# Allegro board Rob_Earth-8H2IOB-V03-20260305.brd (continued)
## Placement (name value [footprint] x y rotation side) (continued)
HOLE3601  -  [HOLE-C5_0D2_2]  47.5 86.5 0 top
HOLE3602  -  [HOLE-C5_0D2_2]  195 5 0 top
HOLE3603  -  [HOLE-C5_0D2_2]  140 5 0 top
HOLE3604  -  [HOLE-C5_0D2_2]  120.5 20 0 top
HOLE3605  -  [HOLE-C5_0D2_2]  47.5 3 0 top
HOLE3606  -  [HOLE-C5_0D2_2]  5 5 0 top
HOLE3607  -  [HOLE-C5_0D2_2]  195 125 0 top
HOLE3608  -  [HOLE-C5_0D2_2]  120.5 86.5 0 top
HOLE3609  -  [HOLE-C5_0D2_2]  140 125 0 top
HOLE3610  -  [HOLE-C5_0D2_2]  60 125 0 top
HOLE3611  -  [HOLE-C5_0D2_2]  5 125 0 top
J501  039301040  [HD2X2-H10-123-39-30-1040]  185.13 20.84 90 top
J1200  161655051  [HDMI19-H16_4-161655051]  7.5 21.15 270 top
J1201  161655051  [HDMI19-H16_4-161655051]  7.5 33.52 270 top
J1300  161655051  [HDMI19-H16_4-161655051]  7.5 45.9 270 top
J1500  LB2016RJ10P1330-11  [RJ45-14P-H13_3-LB2016RJ10P1330-11]  8.7 108.97 270 top
J1600  53398067  [WTB6U-1_25H5_7-53398]  131.25 91.76 270 top
J1900  LB-US3RJ01-02  [CON30-H31-LB-US3RJ02-01]  194.75 85.66 90 top
J1901  LB-US3RJ01-02  [CON30-H31-LB-US3RJ02-01]  194.75 107.61 90 top
J2000  LB-US3RJ01-02  [CON30-H31-LB-US3RJ02-01]  194.75 41.76 90 top
J2001  LB-US3RJ01-02  [CON30-H31-LB-US3RJ02-01]  194.75 63.7 90 top
J2600  SEAF-40-06.0-S-06-2-A-K-TR  [BTB240F-1_27H6_05-SEAF-40]  50 45 90 top
J2700  SEAF-20-06.0-L-10-2-A-K-TR  [BTB200F-1_27H6_05-SEAF-20]  115.5 40 270 top
J2800  BS-08-B2AA001  [BAT2-25_2X20H5_3]  79.49 23.34 0 bottom
J2801  SM02B-PASS-TB  [WTB2S-2H5_7-SM03B-PASS-TB]  87.16 124.24 0 top
J2802  SM02B-PASS-TB  [WTB2S-2H5_7-SM03B-PASS-TB]  75.76 124.24 0 top
J3301  533980271  [WTB2U-1_25H5_7-53398]  98.9 125.44 180 top
J3302  533980271  [WTB2U-1_25H5_7-53398]  131.22 125.46 180 top
J3303  533980371  [WTB3U-1_25H5_7-53398]  150.44 125.4 180 top
J3304  533980271  [WTB2U-1_25H5_7-53398]  120.32 125.45 180 top
J3305  533980271  [WTB2U-1_25H5_7-53398]  109.62 125.45 180 top
J3310  533980571  [WTB5U-1_25H5_7-53398]  163.73 125.41 180 top
J3400  BRA-ST-20102001S-2.8  [HDS2X10-2H6_8-123-BRA-ST]  143.85 34.57 180 top
J3500  53398067  [WTB6U-1_25H5_7-53398]  44.93 125.37 180 top
J3501  53398067  [WTB6U-1_25H5_7-53398]  26.5 125.45 180 top
J3600  47053-1000  [HD4X1-2_54H10-47053-1000]  183.29 3.71 180 top
J3601  47053-1000  [HD4X1-2_54H10-47053-1000]  168.08 3.71 180 top
JP502  Short_L1  [SP2-L1]  120.83 62.15 0 bottom
JP503  Short_L1  [SP2-L1]  120.07 62.48 90 bottom
JP504  Short_L1  [SP2-L1]  99.35 87.08 270 bottom
JP505  Short_L1  [SP2-L1]  99.36 88.24 90 bottom
JP600  Short_L1  [SP2-L1]  67.95 59.67 0 bottom
JP601  Short_L1  [SP2-L1]  65.95 59.67 180 bottom
JP900  power-Short_L5  [SP2-L3P]  40.14 28.08 90 bottom
JP901  power-Short_L5  [SP2-L3P]  28.94 22.6 90 bottom
JP902  power-Short_L5  [SP2-L3P]  28.37 20.41 180 bottom
JP903  power-Short_L5  [SP2-L3P]  31.26 20.07 90 bottom
JP904  power-Short_L5  [SP2-L3P]  30.65 15.72 270 bottom
JP905  power-Short_L5  [SP2-L3P]  30.62 24.84 90 bottom
JP906  power-Short_L5  [SP2-L3P]  38.13 27.72 180 bottom
JP907  power-Short_L5  [SP2-L3P]  36.9 29.06 270 bottom
JP908  power-Short_L5  [SP2-L3P]  31.2 21.83 90 bottom
JP909  power-Short_L5  [SP2-L3P]  38.97 14.54 270 bottom
JP1000  power-Short_L5  [SP2-L3P]  51.63 25.68 90 bottom
JP1001  power-Short_L5  [SP2-L3P]  60.57 28.44 180 bottom
JP1002  power-Short_L5  [SP2-L3P]  60.59 30.14 180 bottom
JP1003  power-Short_L5  [SP2-L3P]  61.61 30.97 0 bottom
JP1004  power-Short_L5  [SP2-L3P]  61.11 34.65 90 bottom
JP1005  power-Short_L5  [SP2-L3P]  61.13 25.9 270 bottom
JP1006  power-Short_L5  [SP2-L3P]  52.87 22.95 180 bottom
JP1007  power-Short_L5  [SP2-L3P]  52.18 24.09 180 bottom
JP1008  power-Short_L5  [SP2-L3P]  60.58 29.29 180 bottom
JP1009  power-Short_L5  [SP2-L3P]  56.31 37.56 0 bottom
JP1100  power-Short_L5  [SP2-L3P]  36.37 36.05 90 bottom
JP1101  power-Short_L5  [SP2-L3P]  45.18 38.99 180 bottom
JP1102  power-Short_L5  [SP2-L3P]  47.37 40.68 180 bottom
JP1103  power-Short_L5  [SP2-L3P]  35.08 42.78 90 bottom
JP1104  power-Short_L5  [SP2-L3P]  46.32 44.85 0 bottom
JP1105  power-Short_L5  [SP2-L3P]  46.25 35.83 0 bottom
JP1106  power-Short_L5  [SP2-L3P]  37.71 33.38 0 bottom
JP1107  power-Short_L5  [SP2-L3P]  37.17 35.96 90 bottom
JP1108  power-Short_L5  [SP2-L3P]  45.29 39.83 180 bottom
JP1109  power-Short_L5  [SP2-L3P]  37.32 47.37 90 bottom
L500  10uH/16A  [SL-SQ16_9H7-TMPC1707HP]  155.02 16.34 90 bottom
L501  1.5uH/15.6A  [SL-10_7X10H5_4]  110.75 67.7 180 bottom
L502  1.5uH/15.6A  [SL-10_7X10H5_4]  108.88 80.97 90 bottom
L503  10uH/16A  [SL-SQ16_9H7-TMPC1707HP]  160.32 19.63 270 top
L600  2.2uH/12A  [SL-10_7X10H4_0]  74.38 67.76 180 bottom
L700  4.7uH/25.4A  [SL-11_9X11H10_0]  99.6 49.15 180 bottom
L800  4.7uH  [SL5020-3-5_4X5_1H2]  115.33 12.45 0 bottom
L801  1uH/4.4A  [SL2016-1_85H0_8]  53.7 43.54 180 bottom
L802  0.47uH  [SL2520-1_7H1_2]  52.19 110.8 270 bottom
L803  1uH/4.4A  [SL2016-1_85H0_8]  142.15 88.22 270 top
L1400  2.2uH/2.6A  [SL2016-1_85H0_8]  89.58 111.54 90 top
L1700  2.2uH/2.6A  [SL2016-1_85H0_8]  137.95 57.94 90 top
L2800  10uH/7.2A  [SL-7_3X7_3H5_4-TMPV0754SV]  93.3 114.9 90 bottom
L2801  10uH/7.2A  [SL-7_3X7_3H5_4-TMPV0754SV]  85.5 114.9 90 bottom
L2802  10uH/7.2A  [SL-7_3X7_3H5_4-TMPV0754SV]  77.75 114.9 90 bottom
L2803  10uH/7.2A  [SL-7_3X7_3H5_4-TMPV0754SV]  69.95 114.9 90 bottom
L2900  22uH/1.28A  [SL-4_0X4_0H1_2]  20.91 99.2 0 bottom
L2901  0.56uH/1.2A  [SL0805H1_0]  16.93 97.81 0 bottom
L2902  22uH/1.28A  [SL-4_0X4_0H1_2]  22.4 92.32 0 bottom
L2903  0.56uH/1.2A  [SL0805H1_0]  18.35 91.82 0 bottom
L2904  22uH/1.28A  [SL-4_0X4_0H1_2]  20.84 86.88 0 bottom
L2905  0.56uH/1.2A  [SL0805H1_0]  16.77 87.76 0 bottom
L2906  22uH/1.28A  [SL-4_0X4_0H1_2]  22.2 80.62 0 bottom
L2907  0.56uH/1.2A  [SL0805H1_0]  18.22 81.84 0 bottom
L3000  22uH/1.28A  [SL-4_0X4_0H1_2]  18.85 76.12 0 bottom
L3001  0.56uH/1.2A  [SL0805H1_0]  16.5 73.03 0 bottom
L3002  22uH/1.28A  [SL-4_0X4_0H1_2]  22.86 68.4 0 bottom
L3003  0.56uH/1.2A  [SL0805H1_0]  17.98 66.94 0 bottom
L3004  22uH/1.28A  [SL-4_0X4_0H1_2]  21.28 62.85 0 bottom
L3005  0.56uH/1.2A  [SL0805H1_0]  17.84 62.35 90 bottom
L3006  22uH/1.28A  [SL-4_0X4_0H1_2]  22.52 56.06 0 bottom
L3007  0.56uH/1.2A  [SL0805H1_0]  18.52 56.89 0 bottom
L3200  1uH/4.4A  [SL2016-1_85H0_8]  53.28 65.72 180 bottom
LED500  RED  [LED0603H0_4]  101.48 94.88 180 top
LED1700  YELLOW GREEN  [LED0603X2H0_35]  132.28 54.53 0 top
LED3101  BLUE  [LED0603H0_8]  41.05 61.38 180 top
M3602  0.5mm  [MARK]  11.67 8.38 180 bottom
M3603  0.5mm  [MARK]  189.22 121.46 180 bottom
M3605  0.5mm  [MARK]  191.29 10.06 0 top
M3606  0.5mm  [MARK]  9.61 121.67 0 top
NOREF  -  [unnamed]  52 3 0 top
NOREF#2  -  [unnamed]  195 11 0 top
NOREF#3  -  [#2]  45.7 100.77 0 top
NOREF#4  -  [unnamed]  116 86.5 0 top
NOREF#5  -  [unnamed]  13 125 0 top
NUT2301  JYJ5034520043  [NUT-C5_2D2_8H3_1]  153.29 120.13 0 bottom
Q501  DMT69M5LCG-7  [DFN3333-8-H0_8]  96.01 81.23 180 bottom
Q502  DMT69M5LCG-7  [DFN3333-8-H0_8]  99.5 67.6 90 bottom
Q503  DMT69M5LCG-7  [DFN3333-8-H0_8]  100.48 75.87 180 bottom
Q504  DMT69M5LCG-7  [DFN3333-8-H0_8]  101.8 62.15 0 bottom
Q505  DMT69M5LCG-7  [DFN3333-8-H0_8]  144.15 23.05 90 bottom
Q506  DMT69M5LCG-7  [DFN3333-8-H0_8]  137.75 25.35 180 bottom
Q507  LMBT3904LT1G  [SOT23H1_1]  139.2 15.95 0 bottom
Q600  DMT69M5LCG-7  [DFN3333-8-H0_8]  79.64 55.78 0 bottom
Q601  DMT69M5LCG-7  [DFN3333-8-H0_8]  75.08 60.21 90 bottom
Q700  DMT69M5LCG-7  [DFN3333-8-H0_8]  110.15 39.1 90 bottom
Q701  DMT69M5LCG-7  [DFN3333-8-H0_8]  106.05 39.25 90 bottom
Q702  DMT69M5LCG-7  [DFN3333-8-H0_8]  91.95 37.95 270 bottom
Q703  DMT69M5LCG-7  [DFN3333-8-H0_8]  96.1 41.25 270 bottom
Q1400  WM02N08F  [DFN1006-3-H0_55]  104.44 112.04 180 top
Q3101  LN2306EFLT1G  [SOT23H1_1]  40.36 58.98 0 top
R500  100K_2  [0402]  125.45 22.21 180 bottom
R501  2.2K_2  [0402]  130.45 21.56 0 bottom
R502  0_2  [0402]  91.81 77.84 90 bottom
R503  3.3/F_2  [0402]  93.25 66.62 180 bottom
R504  0R003/F_2512  [SR2512H0_65]  122.72 66.12 180 bottom
R505  3.3/F_2  [0402]  93.95 77.49 180 bottom
R506  0R003/F_2512  [SR2512H0_65]  101.7 87.5 90 bottom
R507  0_2  [0402]  89.3 67.4 90 bottom
R508  0_2  [0402]  90.16 77.83 270 bottom
R509  0_2  [0402]  86.14 71.46 0 bottom
R510  0_2  [0402]  86.14 72.31 0 bottom
R511  0_2  [0402]  84.86 71.43 270 bottom
R512  18.7K/F_2  [0402]  87.64 67.4 270 bottom
R513  49.9K/F_2  [0402]  86.14 74.04 180 bottom
R514  RES_PAD_6  [1206_SP]  132.13 27.38 90 top
R515  10K_2  [0402]  92.78 77.83 270 bottom
R516  RES_PAD_6  [1206_SP]  171.65 8.4 270 bottom
R517  0R010/F_6  [SR1206]  115.55 49.75 90 bottom
R518  0R010/F_6  [SR1206]  90.65 85.75 90 bottom
R519  NC 0R010/F_6  [SR1206]  143.95 26.3 180 bottom
R520  100K/F_2  [0402]  179.53 123.71 90 top
R521  10K_2  [0402]  129.82 19.67 270 bottom
R522  15K_2  [0402]  131.3 10.72 90 bottom
R523  10K_2  [0402]  130.67 19.67 270 bottom
R524  3.3/F_2  [0402]  175.11 124.64 0 top
R525  3.3/F_2  [0402]  175.12 123.74 180 top
R526  10K_2  [0402]  178.2 127.4 180 top
R527  2.2K_2  [0402]  133.3 16.2 180 bottom
R528  27K/F_2  [0402]  177.77 124.5 90 top
R529  100_2  [0402]  127.05 19.7 90 bottom
R530  10K/F_2  [0402]  178.18 126.55 0 top
R531  10K_2  [0402]  136 19.05 180 bottom
R532  10K_2  [0402]  92.08 67.55 90 bottom
R533  NC 10K_2  [0402]  86.45 76.1 270 bottom
R534  1K_2  [0402]  102.19 92.79 270 top
R535  34.8K/F_2  [0402]  178.62 124.5 90 top
R536  39K/F_2  [0402]  178.18 125.7 0 top
R537  3.3/F_2  [0402]  125.39 30.4 180 top
R538  1K_2  [0402]  127.23 39.87 0 top
R539  0_2  [0402]  92.25 79.48 270 bottom
R540  14K/F_2  [0402]  89.31 77.84 90 bottom
R541  100K/F_2  [0402]  90.95 67.4 270 bottom
R542  NC 0_2  [0402]  90.12 67.4 90 bottom
R543  243K/F_2  [0402]  88.46 65.85 270 bottom
R544  14K/F_2  [0402]  89.31 65.86 270 bottom
R600  NC 10K_2  [0402]  73.84 52.86 0 bottom
R601  1/F_2  [0402]  73.84 54.11 0 bottom
R602  10K_2  [0402]  69.59 57.36 180 bottom
R603  NC 10K_2  [0402]  71.89 49.81 90 bottom
R604  10K_2  [0402]  69.94 49.81 90 bottom
R605  0R010/F_6  [SR1206]  66.96 61.39 180 bottom
R606  1/F_2  [0402]  71.64 57.71 90 bottom
R607  86.6K/F_2  [0402]  66.19 54.01 0 bottom
R608  NC 0_2  [0402]  68.79 58.21 180 bottom
R609  0R010/F_6  [SR1206]  85.35 57.3 270 bottom
R610  0_2  [0402]  71.04 49.81 270 bottom
R611  NC 100K_2  [0402]  69.09 49.81 270 bottom
R612  10K/F_2  [0402]  66.18 55.7 180 bottom
R613  34.8K/F_2  [0402]  68.24 49.81 270 bottom
R614  100K_2  [0402]  66.19 52.16 180 bottom
R700  0R010/F_6  [SR1206]  121.6 38.45 180 bottom
R701  10/F_2  [0402]  106.05 35.5 180 bottom
R702  10/F_2  [0402]  107.23 35.85 90 bottom
R703  0R002/F_6  [SR1206]  104.9 42.2 180 bottom
R704  NC 10K_2  [0402]  105.13 24.85 270 bottom
R705  NC 10K_2  [0402]  103.33 24.85 90 bottom
R706  9.09K/F_2  [0402]  104.23 24.85 270 bottom
R707  130K/F_2  [0402]  95.65 30.4 270 bottom
R708  9.09K/F_2  [0402]  97.43 23.15 270 bottom
R709  8.25K/F_2  [0402]  101.03 24.75 270 bottom
R710  110K/F_2  [0402]  100.13 24.75 270 bottom
R711  84.5K/F_2  [R0402]  99.23 24.75 270 bottom
R712  5.62K/F_2  [0402]  95.65 28.85 270 bottom
R713  49.9K/F_2  [0402]  125.35 14.17 90 bottom
R714  49.9K/F_2  [0402]  125.35 15.77 90 bottom
R800  243K/F_2  [0402]  127.84 6.6 90 bottom
R801  27K/F_2  [0402]  127.83 8.15 90 bottom
R802  330K_2  [0402]  119.8 9.25 0 bottom
R803  10K_2  [0402]  121.8 9.59 90 bottom
R804  243K/F_2  [0402]  120.97 9.59 90 bottom
R805  33K/F_2  [0402]  54.18 38.46 90 bottom
R806  1K_2  [0402]  56.9 38.47 90 bottom
R808  47K/F_2  [0402]  53.32 38.46 270 bottom
R810  5.9K/F_2  [0402]  48.25 58.1 270 bottom
R811  5.9K/F_2  [0402]  48.3 53.47 270 bottom
R812  100K/F_2  [0402]  58.11 110.46 180 bottom
R813  1K_2  [0402]  58.11 114 180 bottom
R815  47K/F_2  [0402]  58.11 112.18 0 bottom
R816  39K/F_2  [0402]  136.83 87.58 0 top
R817  1K_2  [0402]  136.85 91.43 0 top
R818  100K_2  [0402]  136.85 89.73 180 top
R819  47K/F_2  [0402]  136.83 88.41 180 top
R820  5.9K/F_2  [0402]  138.44 98.33 0 top
R821  1K_2  [0402]  55.35 53.5 90 bottom
R896  NC 1K_2  [0402]  56.9 40.22 270 bottom
R898  NC 1K_2  [0402]  54.47 53.5 90 bottom
R899  1M_2  [0402]  64.65 51.07 0 bottom
R900  22_2  [0402]  30.25 18.65 180 bottom
R901  22_2  [0402]  30.25 17.8 180 bottom
R902  0_1  [0201]  33.01 25.92 270 bottom
R903  2.2_1  [0201]  32.36 14.79 270 bottom
R904  0_1  [0201]  33.59 25.92 270 bottom
R905  2.2_1  [0201]  32.94 14.8 270 bottom
R906  2.2_1  [0201]  33.51 14.8 270 bottom
R907  0_1  [0201]  34.44 25.92 270 bottom
R908  2.2_1  [0201]  34.11 14.8 270 bottom
R909  0_1  [0201]  35 25.92 270 bottom
R910  1K_2  [0402]  30.21 27.45 270 bottom
R911  100K_2  [0402]  29.36 27.44 270 bottom
R912  0_1  [0201]  35.72 25.92 270 bottom
R913  2.2_1  [0201]  35.57 14.81 270 bottom
R914  2.2K_2  [0402]  19.72 13.73 90 top
R915  2.2K_2  [0402]  20.57 13.74 90 top
R916  0_1  [0201]  36.32 25.92 270 bottom
R917  2.2_1  [0201]  36.15 14.82 270 bottom
R918  2.2_1  [0201]  36.72 14.82 270 bottom
R919  0_1  [0201]  37.14 25.92 270 bottom
R920  2.2_1  [0201]  37.29 14.82 270 bottom
R921  0_1  [0201]  37.7 25.92 270 bottom
R922  10.5K/F_2  [0402]  38.13 14.62 270 bottom
R923  10K_2  [0402]  40.67 14.62 270 bottom
R924  NC 10K_2  [0402]  43.86 16.27 180 bottom
R925  4.7K_2  [0402]  29.94 31.93 180 bottom
R926  10K_2  [0402]  42.32 16.26 0 bottom
R927  10K_2  [0402]  42.36 22.71 180 bottom
R928  22_2  [0402]  42.33 18.8 0 bottom
R929  22_2  [0402]  42.33 19.63 0 bottom
R930  22K_2  [0402]  42.35 21.04 0 bottom
R931  1M_2  [0402]  28.05 22.37 90 bottom
R932  1M_2  [0402]  28.95 23.97 90 bottom
R933  100K_2  [0402]  28.95 22.37 270 bottom
R934  100K_2  [0402]  28.05 23.97 270 bottom
R1000  22_2  [0402]  61.53 31.81 0 bottom
R1001  22_2  [0402]  61.55 32.65 0 bottom
R1002  0_1  [0201]  58.85 24.62 90 bottom
R1003  0_1  [0201]  58.27 24.62 90 bottom
R1004  2.2_1  [0201]  59.21 35.6 90 bottom
R1005  2.2_1  [0201]  58.64 35.59 90 bottom
R1006  2.2_1  [0201]  58.04 35.59 90 bottom
R1007  0_1  [0201]  57.4 24.62 90 bottom
R1008  2.2_1  [0201]  57.46 35.59 90 bottom
R1009  0_1  [0201]  56.84 24.62 90 bottom
R1010  0_1  [0201]  56.12 24.63 90 bottom
R1011  2.2_1  [0201]  56 35.58 90 bottom
R1012  0_1  [0201]  55.52 24.63 90 bottom
R1013  2.2_1  [0201]  55.43 35.57 90 bottom
R1014  2.2_1  [0201]  54.84 35.57 90 bottom
R1015  0_1  [0201]  54.64 24.62 90 bottom
R1016  2.2_1  [0201]  54.27 35.57 90 bottom
R1017  0_1  [0201]  54.07 24.62 90 bottom
R1018  10.5K/F_2  [0402]  53.45 35.77 90 bottom
R1019  10K_2  [0402]  50.91 35.77 90 bottom
R1020  NC 10K_2  [0402]  47.7 33.49 0 bottom
R1021  10K_2  [0402]  49.37 33.5 180 bottom
R1022  10K_2  [0402]  49.33 27.7 0 bottom
R1023  22_2  [0402]  49.36 31 180 bottom
R1024  22_2  [0402]  49.36 30.16 180 bottom
R1025  22K_2  [0402]  49.34 28.6 180 bottom
R1026  1K_2  [0402]  58.71 20.05 180 bottom
R1027  100K_2  [0402]  58.7 20.9 180 bottom
R1028  4.7K_2  [0402]  61.6 21.74 0 bottom
R1029  1M_2  [0402]  62.75 26.57 270 bottom
R1030  1M_2  [0402]  63.65 28.17 270 bottom
R1031  100K_2  [0402]  62.75 28.17 90 bottom
R1032  100K_2  [0402]  63.65 26.57 90 bottom
R1100  22_2  [0402]  46.26 42.35 0 bottom
R1101  22_2  [0402]  46.25 43.2 0 bottom
R1102  0_1  [0201]  43.5 35.16 90 bottom
R1103  2.2_1  [0201]  43.94 46.14 90 bottom
R1104  0_1  [0201]  42.92 35.16 90 bottom
R1105  2.2_1  [0201]  43.37 46.14 90 bottom
R1106  0_1  [0201]  42.07 35.16 90 bottom
R1107  2.2_1  [0201]  42.79 46.14 90 bottom
R1108  2.2_1  [0201]  42.19 46.14 90 bottom
R1109  0_1  [0201]  41.51 35.16 90 bottom
R1110  0_1  [0201]  40.84 35.17 90 bottom
R1111  2.2_1  [0201]  40.73 46.13 90 bottom
R1112  0_1  [0201]  40.27 35.17 90 bottom
R1113  2.2_1  [0201]  40.15 46.12 90 bottom
R1114  2.2K_2  [0402]  29.35 45.75 180 bottom
R1115  2.2K_2  [0402]  29.36 44.23 180 bottom
R1116  2.2_1  [0201]  39.59 46.12 90 bottom
R1117  0_1  [0201]  39.3 35.17 90 bottom
R1118  2.2_1  [0201]  39.02 46.12 90 bottom
R1119  0_1  [0201]  38.73 35.17 90 bottom
R1120  10.5K/F_2  [0402]  38.18 46.31 90 bottom
R1121  10K_2  [0402]  35.64 46.32 90 bottom
R1122  NC 10K_2  [0402]  32.65 43.99 0 bottom
R1123  10K_2  [0402]  34.2 44.05 180 bottom
R1124  10K_2  [0402]  34.24 38.38 0 bottom
R1125  22_2  [0402]  34.19 41.46 180 bottom
R1126  22_2  [0402]  34.19 40.63 180 bottom
R1127  22K_2  [0402]  34.23 39.27 180 bottom
R1128  1K_2  [0402]  48.57 46.21 180 bottom
R1129  100K_2  [0402]  48.56 47.05 180 bottom
R1130  4.7K_2  [0402]  51.46 47.89 0 bottom
R1131  1M_2  [0402]  45.97 37.02 180 bottom
R1132  1M_2  [0402]  47.52 36.17 180 bottom
R1133  100K_2  [0402]  47.52 37.02 0 bottom
R1134  100K_2  [0402]  45.97 36.17 0 bottom
R1200  NC 0_1  [0201]  11.82 14.03 90 top
R1201  2.2K_2  [0402]  27.16 36.41 270 top
R1202  2.2K_2  [0402]  27.99 36.4 270 top
R1209  NC 0_1  [0201]  12.37 14.04 90 top
R1210  NC 0_1  [0201]  13.32 14.04 90 top
R1211  NC 0_1  [0201]  13.87 14.03 90 top
R1212  NC 0_1  [0201]  14.87 14.03 90 top
R1214  NC 0_1  [0201]  15.42 14.03 90 top
R1215  NC 0_1  [0201]  16.37 14.04 90 top
R1216  NC 0_1  [0201]  16.92 14.04 90 top
R1217  NC 0_1  [0201]  25.65 28.5 180 top
R1226  NC 0_1  [0201]  25.65 29.05 180 top
R1227  NC 0_1  [0201]  25.65 30 180 top
R1228  NC 0_1  [0201]  25.65 30.55 180 top
R1229  NC 0_1  [0201]  25.65 31.65 180 top
R1231  NC 0_1  [0201]  25.65 32.2 180 top
R1232  NC 0_1  [0201]  25.65 33.14 180 top
R1233  NC 0_1  [0201]  25.65 33.69 180 top
R1297  47K_2  [0402]  25.15 50.22 90 top
R1298  47K_2  [0402]  24 37.57 0 top
R1299  47K_2  [0402]  22.8 15.69 270 top
R1300  NC 0_1  [0201]  25.33 41.27 180 top
R1309  NC 0_1  [0201]  25.33 41.82 180 top
R1310  NC 0_1  [0201]  25.33 42.76 180 top
R1311  NC 0_1  [0201]  25.33 43.32 180 top
R1312  NC 0_1  [0201]  25.33 44.32 180 top
R1314  NC 0_1  [0201]  25.33 44.87 180 top
R1315  NC 0_1  [0201]  25.33 45.82 180 top
R1316  NC 0_1  [0201]  25.33 46.37 180 top
R1400  75_2  [0402]  122.55 95.68 180 top
R1401  2.49K/F_2  [0402]  104.45 101.87 270 top
R1402  75_2  [0402]  119.59 95.68 180 top
R1403  2.2K_2  [0402]  93.7 104.56 0 top
R1404  75_2  [0402]  116.64 95.67 180 top
R1405  0_2  [0402]  93.7 105.37 0 top
R1406  75_2  [0402]  113.65 95.68 180 top
R1407  10K_2  [0402]  103.3 112.44 270 top
R1408  NC 1M_2  [0402]  101.56 102.34 180 top
R1409  1.5K_2  [0402]  100.02 112.44 270 top
R1410  0_2  [0402]  100.84 112.44 270 top
R1411  0_2  [0402]  101.66 112.45 270 top
R1412  0_2  [0402]  106.73 102.9 180 top
R1413  0_2  [0402]  106.73 104.66 180 top
R1414  NC 10K_2  [0402]  93.64 109.9 180 top
R1415  NC 10K_2  [0402]  93.64 108.95 180 top
R1416  10K_2  [0402]  93.7 103.64 180 top
R1417  NC 10K_2  [0402]  93.63 110.84 0 top
R1418  10K_2  [0402]  93.64 111.74 0 top
R1419  10K_2  [0402]  96.74 112.36 270 top
R1420  NC 10K_2  [0402]  97.59 112.36 270 top
R1421  10K_2  [0402]  95.29 101.47 90 top
R1422  NC 10K_2  [0402]  93.69 102.76 0 top
R1423  0_2  [0402]  90.82 114.33 90 top
R1424  10K_2  [0402]  92.11 109.9 0 top
R1425  10K_2  [0402]  92.07 108.95 0 top
R1426  NC 10K_2  [0402]  92.14 103.64 0 top
R1427  10K_2  [0402]  92.1 110.83 0 top
R1428  NC 10K_2  [0402]  92.11 111.74 0 top
R1429  NC 10K_2  [0402]  96.74 113.9 270 top
R1430  10K_2  [0402]  97.6 113.9 90 top
R1431  NC 10K_2  [0402]  94.44 101.48 270 top
R1432  10K_2  [0402]  92.14 102.75 180 top
R1433  0_2  [0402]  89.75 114.33 90 top
R1434  NC 1.5K_2  [0402]  98.98 101.1 270 top
R1435  NC 1.5K_2  [0402]  98.17 101.1 270 top
R1436  NC 1.5K_2  [0402]  98.57 102.29 180 top
R1500  0_2  [0402]  32.8 113.67 270 top
R1501  0_2  [0402]  16.6 97.3 0 top
R1502  330_2  [0402]  34.1 113.77 90 top
R1503  2.49K/F_2  [0402]  31 113.67 270 top
R1504  10K_2  [0402]  37.05 111.47 0 top
R1505  10K_2  [0402]  38.25 111.07 90 top
R1506  0_2  [0402]  37.05 110.62 0 top
R1507  0_2  [0402]  37.05 109.77 0 top
R1508  0_2  [0402]  37.05 108.92 0 top
R1509  10K_2  [0402]  32.4 106.07 0 top
R1510  0_2  [0402]  32.4 105.22 0 top
R1511  0_1  [0201]  33.75 105.97 90 top
R1512  0_2  [0402]  29 117.27 180 top
R1513  0_1  [0201]  34.35 105.97 90 top
R1514  330_2  [0402]  34.97 113.76 90 top
R1515  NC 0_2  [0402]  39.85 112.13 0 top
R1516  1.02M/F_6  [SR1206]  23 115.85 180 top
R1517  0_2  [0402]  42.85 118.58 0 top
R1518  10K_2  [0402]  43.28 112.23 180 top
R1519  NC 10K_2  [0402]  42.85 117.73 0 top
R1520  0_2  [0402]  41.2 108.81 270 top
R1521  NC 10K_2  [0402]  43.01 107.51 180 top
R1522  0_2  [0402]  47.97 105.99 0 top
R1523  NC 0_2  [0402]  43 106.64 180 top
R1600  4.7K_2  [0402]  126.41 65.88 0 top
R1601  10K_2  [0402]  138.3 79.67 180 top
R1602  10K_2  [0402]  136.41 74.95 270 top
R1603  1K_2  [0402]  126.62 59.78 180 top
R1604  0_2  [0402]  137.24 74.95 270 top
R1605  10K_2  [0402]  139.95 75.06 270 top
R1606  0_2  [0402]  140.79 75.07 270 top
R1607  100K_2  [0402]  126.72 82.18 270 top
R1608  4.7K_2  [0402]  127.5 76.86 180 top
R1609  10K_2  [0402]  130.05 61.02 90 top
R1610  NC 1.5K_2  [0402]  130.99 64.68 270 top
R1611  NC 1.5K_2  [0402]  130.15 64.69 270 top
R1612  10K_2  [0402]  129.31 75.86 0 top
R1613  0_2  [0402]  130.57 73.34 180 top
R1614  0_2  [0402]  130.57 74.2 180 top
R1615  10K_2  [0402]  127.5 75.86 180 top
R1616  10K_2  [0402]  132.76 81.74 0 top
R1617  0_2  [0402]  132.76 80.08 180 top
R1618  0_2  [0402]  132.77 80.91 180 top
R1619  10K_2  [0402]  130.86 83.15 90 top
R1620  10K_2  [0402]  130.01 83.15 90 top
R1700  100K_2  [0402]  153.7 53.5 0 top
R1701  1.5K_2  [0402]  154.93 53.99 90 top
R1702  NC 10K_2  [0402]  156.6 47.92 270 top
R1703  1.5K_2  [0402]  155.78 53.99 90 top
R1704  NC 4.7K_2  [0402]  148.33 53.08 90 top
R1705  4.7K_2  [0402]  148.33 51.55 270 top
R1706  4.7K_2  [0402]  147.46 53.08 90 top
R1707  NC 4.7K_2  [0402]  147.46 51.56 270 top
R1708  4.7K_2  [0402]  146.56 53.08 270 top
R1709  4.7K_2  [0402]  145.66 53.08 90 top
R1710  NC 4.7K_2  [0402]  145.66 51.54 270 top
R1711  NC 4.7K_2  [0402]  144.77 53.07 90 top
R1712  4.7K_2  [0402]  144.76 51.54 270 top
R1713  NC 4.7K_2  [0402]  143.94 53.07 270 top
R1714  NC 4.7K_2  [0402]  143.01 53.07 90 top
R1715  4.7K_2  [0402]  143.01 51.55 270 top
R1716  2.49K/F_2  [0402]  153.59 75.51 90 top
R1717  1K_2  [0402]  151.11 75.51 90 top
R1718  1K_2  [0402]  151.94 75.51 90 top
R1719  330_2  [0402]  131.99 55.57 0 top
R1720  1K_2  [0402]  140.22 58.73 0 top
R1721  NC 1K_2  [0402]  140.22 57.9 180 top
R1722  4.7K_2  [0402]  131.98 56.57 0 top
R1800  0_1  [0201]  148.15 85.87 0 top
R1801  0_1  [0201]  148.15 85.27 0 top
R1802  2.2K_2  [0402]  107.45 20.15 0 bottom
R1803  2.2K_2  [0402]  107.45 19.3 0 bottom
R1804  330_2  [0402]  127.45 57.87 0 top
R1805  47K/F_2  [0402]  128.65 54.87 0 top
R1806  15K/F_2  [0402]  130.25 54.87 0 top
R1809  10K_2  [0402]  137.07 29.02 0 top
R1810  10K_2  [0402]  135.46 29.01 180 top
R1811  10K_2  [0402]  141.75 102.27 90 top
R1812  10K_2  [0402]  162.15 115.67 90 top
R1813  10K_2  [0402]  146.6 109.97 90 top
R1814  10K_2  [0402]  148.05 108.12 0 top
R1900  0_2  [0402]  169.04 91.55 270 top
R1901  0_2  [0402]  167.17 113.94 270 top
R1902  330_2  [0402]  167.81 90.43 0 top
R1903  330_2  [0402]  165.99 112.82 0 top
R1904  4.7K_2  [0402]  167.17 112.42 90 top
R1905  4.7K_2  [0402]  167.81 91.25 0 top
R1906  NC 330_2  [0402]  170.84 77.62 0 top
R1907  330_2  [0402]  171.14 101.25 0 top
R1908  NC 0_2  [0402]  170.83 79.29 0 top
R1909  0_2  [0402]  171.99 102.11 0 top
R1910  1.02M/F_6  [SR1206]  170.66 96.04 180 top
R1911  1.02M/F_6  [SR1206]  170.65 118.62 180 top
R1912  330_2  [0402]  170.83 78.47 0 top
R1913  0_2  [0402]  170.81 80.12 0 top
R2000  0_2  [0402]  169.99 69.45 0 top
R2001  4.7K_2  [0402]  168.45 67.38 0 top
R2002  330_2  [0402]  168.45 68.22 0 top
R2003  330_2  [0402]  168.77 44.22 0 top
R2004  330_2  [0402]  170.75 57.02 0 top
R2005  330_2  [0402]  170.68 34.57 0 top
R2006  0_2  [0402]  170.75 57.92 180 top
R2007  4.7K_2  [0402]  168.77 43.41 0 top
R2009  0_2  [0402]  169.62 45.07 0 top
R2010  1.02M/F_6  [SR1206]  170.2 73.17 180 top
R2011  1.02M/F_6  [SR1206]  170.3 51.77 180 top
R2012  NC 330_2  [0402]  170.7 35.43 0 top
R2013  0_2  [0402]  170.69 36.25 0 top
R2015  NC 0_2  [0402]  170.7 37.09 0 top
R2300  0_2  [0402]  144.05 33.99 90 bottom
R2301  100K_2  [0402]  125.55 39.87 180 top
R2302  22_2  [0402]  107.6 98.85 270 bottom
R2303  1K_2  [0402]  123.95 41.67 0 top
R2307  10K_2  [0402]  131.64 49.05 270 top
R2308  0_2  [0402]  163.1 33.99 90 bottom
R2309  10K_2  [0402]  128.12 49.03 90 top
R2399  NC 1K_2  [0402]  125.55 41.67 180 top
R2400  NC 1M_2  [0402]  147.37 92.03 270 top
R2401  10K_2  [0402]  148.54 94.71 0 top
R2402  100K_2  [0402]  158.28 78.33 0 top
R2403  4.7K_2  [0402]  163.29 79.56 270 top
R2404  15K_2  [0402]  148.35 78.57 270 top
R2405  4.7K_2  [0402]  154.18 82.42 90 top
R2406  4.7K_2  [0402]  155.02 82.42 90 top
R2407  100K_2  [0402]  149.55 78.17 0 top
R2408  12.4K/F_2  [0402]  148.56 90.29 180 top
R2409  4.7K_2  [0402]  158.45 83.35 270 top
R2410  4.7K_2  [0402]  148.56 93.77 0 top
R2411  4.7K_2  [0402]  148.57 92.95 180 top
R2412  0_1  [0201]  148.15 84.67 0 top
R2413  0_1  [0201]  148.15 84.07 0 top
R2414  0_2  [0402]  163.64 78.39 0 top
R2415  0_2  [0402]  163.63 77.56 0 top
R2416  0_2  [0402]  158.28 79.17 180 top
R2417  0_2  [0402]  158.27 80.01 180 top
R2418  0_2  [0402]  147.05 78.17 0 top
R2419  10K/F_2  [0402]  96.53 23.15 90 bottom
R2420  0_2  [0402]  96.5 28.85 90 bottom
R2500  1K_2  [0402]  121.83 57.28 180 bottom
R2501  100K_2  [0402]  121.83 56.43 0 bottom
R2502  12.4K/F_2  [0402]  121.79 51.1 0 bottom
R2503  12.4K/F_2  [0402]  137.82 72.84 270 bottom
R2504  12.4K/F_2  [0402]  133.37 72.89 270 bottom
R2505  0_2  [0402]  134.75 48.19 90 bottom
R2506  NC 0_2  [0402]  139.37 51.95 180 bottom
R2507  12.4K/F_2  [0402]  137.67 62.44 270 bottom
R2508  NC 0_2  [0402]  135.97 48.14 270 bottom
R2509  NC 680/F_2  [0402]  136.82 48.14 270 bottom
R2510  12.4K/F_2  [0402]  133.17 62.44 270 bottom
R2511  NC 4.7K_2  [0402]  130.57 51.92 0 bottom
R2512  10K_2  [0402]  130.57 52.82 0 bottom
R2513  10K_2  [0402]  130.57 53.62 0 bottom
R2514  10K_2  [0402]  133.4 57.29 270 bottom
R2515  10K_2  [0402]  134.3 57.29 270 bottom
R2516  NC 10K_2  [0402]  131.62 57.29 270 bottom
R2517  NC 10K_2  [0402]  132.52 57.29 270 bottom
R2518  NC 10K_2  [0402]  131.63 58.84 90 bottom
R2519  NC 10K_2  [0402]  132.53 58.84 90 bottom
R2520  0_2  [0402]  139.24 54.12 180 bottom
R2521  0_2  [0402]  139.24 53.28 180 bottom
R2700  3.3K_2  [0402]  140.83 108.12 90 top
R2701  3.3K_2  [0402]  166.28 118.34 0 top
R2703  10K_2  [0402]  153.36 109.47 270 top
R2704  3.3K_2  [0402]  152.05 111.33 0 top
R2705  3.3K_2  [0402]  149.39 102.1 270 top
R2706  0_2  [0402]  125.45 33.75 0 top
R2707  100K_2  [0402]  143.15 106.87 90 top
R2708  0_2  [0402]  125.32 54.47 180 top
R2709  100K_2  [0402]  164.55 115.67 270 top
R2710  NC 0_1  [0201]  170.41 113.23 0 top
R2711  NC 0_1  [0201]  170.72 110.03 0 top
R2712  NC 0_1  [0201]  170.4 116.65 0 top
R2713  NC 0_1  [0201]  170.41 112.69 0 top
R2714  NC 0_1  [0201]  170.72 109.47 0 top
R2715  NC 0_1  [0201]  170.4 116.09 0 top
R2716  NC 0_1  [0201]  170.41 111.71 0 top
R2717  NC 0_1  [0201]  167.46 116.84 0 top
R2718  NC 0_1  [0201]  170.41 115.14 0 top
R2719  NC 0_1  [0201]  170.41 111.15 0 top
R2720  NC 0_1  [0201]  167.46 116.28 0 top
R2721  NC 0_1  [0201]  170.41 114.59 0 top
R2724  10K_2  [0402]  143.15 105.27 270 top
R2725  100K_2  [0402]  152.45 109.47 270 top
R2728  10K_2  [0402]  152.55 105.82 0 top
R2734  10K_2  [0402]  163.65 115.67 270 top
R2736  NC 0_1  [0201]  170.15 89.09 0 top
R2737  NC 0_1  [0201]  170.48 90.24 0 top
R2738  NC 0_1  [0201]  170.17 93.96 0 top
R2740  NC 0_1  [0201]  170.15 88.55 0 top
R2741  NC 0_1  [0201]  170.48 90.79 0 top
R2742  NC 0_1  [0201]  170.17 93.41 0 top
R2743  NC 0_1  [0201]  170.16 87.64 0 top
R2744  NC 0_1  [0201]  167.32 94.28 0 top
R2745  NC 0_1  [0201]  170.16 92.46 0 top
R2746  NC 0_1  [0201]  170.16 87.08 0 top
R2747  NC 0_1  [0201]  167.32 93.73 0 top
R2748  NC 0_1  [0201]  170.16 91.91 0 top
R2749  100K_2  [0402]  152.55 104.97 0 top
R2800  NC 4.7K_2  [0402]  81.6 96.95 90 bottom
R2801  3.3/F_2  [0402]  86.55 120.7 90 bottom
R2802  3.3/F_2  [0402]  92.85 120.7 90 bottom
R2803  3.3/F_2  [0402]  70.05 120.65 90 bottom
R2804  2K/F_2  [0402]  76.9 120.65 90 bottom
R2805  4.7K_2  [0402]  77.35 96.95 270 bottom
R2806  0_2  [0402]  79.9 96.95 90 bottom
R2807  100K_2  [0402]  108.05 17.9 90 bottom
R2808  1K_2  [0402]  96.15 20.9 0 bottom
R2809  0_2  [0402]  79.05 96.95 90 bottom
R2810  22_2  [0402]  42.26 37.99 180 top
R2811  22_2  [0402]  42.3 36.5 180 top
R2812  NC 0_2  [0402]  42.23 33.08 180 top
R2813  22_2  [0402]  42.23 33.91 180 top
R2816  4.7K_2  [0402]  80.75 96.95 270 bottom
R2817  4.7K_2  [0402]  78.2 96.95 270 bottom
R2818  4.7K_2  [0402]  84.6 96.95 270 bottom
R2820  22_2  [0402]  71.65 97.4 90 bottom
R2900  220nH/1.25A  [SL0603-H1_0]  16.05 95.46 270 bottom
R2901  NC 5.1K_2  [0402]  20.94 101.84 180 bottom
R2902  49.9/F_2  [0402]  36.77 102.74 315 bottom
R2903  220nH/1.25A  [SL0603-H1_0]  16.01 92.59 90 bottom
R2904  NC 5.1K_2  [0402]  22.35 89.62 180 bottom
R2905  49.9/F_2  [0402]  34.41 100.51 315 bottom
R2906  220nH/1.25A  [SL0603-H1_0]  15.93 85.49 270 bottom
R2907  NC 5.1K_2  [0402]  20.75 89.62 180 bottom
R2908  49.9/F_2  [0402]  34.86 91.11 45 bottom
R2909  220nH/1.25A  [SL0603-H1_0]  15.91 82.63 90 bottom
R2910  NC 5.1K_2  [0402]  22.45 77.67 180 bottom
R2911  0_2  [0402]  42.6 83.95 45 bottom
R2912  402/F_2  [0402]  34.23 98.14 135 bottom
R2913  0_2  [0402]  41.91 84.59 45 bottom
R2914  49.9/F_2  [0402]  37.23 88.81 45 bottom
R2915  NC 1M_2  [0402]  33.03 97.54 225 bottom
R2916  NC 10K_2  [0402]  34.77 93.39 225 bottom
R2917  NC 10K_2  [0402]  39.58 88.65 225 bottom
R2918  2.2K_2  [0402]  41.5 82.84 225 bottom
R2919  0_1  [0201]  32.35 96.2 135 bottom
R2920  NC 0_1  [0201]  33.1 96.61 225 bottom
R2921  10K_2  [0402]  33.7 92.28 45 bottom
R2922  10K_2  [0402]  38.47 87.57 45 bottom
R2923  5.1K_2  [0402]  41.45 86.64 225 bottom
R2924  0_1  [0201]  31.92 95.76 315 bottom
R2925  5.1K_2  [0402]  40.22 88.03 225 bottom
R2926  0_2  [0402]  40.38 85.52 225 bottom
R2927  0_2  [0402]  39.09 86.91 225 bottom
R2928  0_2  [0402]  40.84 87.26 225 bottom
R2929  10K_2  [0402]  43.94 103.08 45 bottom
R2930  0_2  [0402]  42.08 86.02 225 bottom
R2931  2.2K_2  [0402]  40.72 83.61 225 bottom
R2932  10K_2  [0402]  30.09 92.51 315 bottom
R3000  220nH/1.25A  [SL0603-H1_0]  15.65 70.73 270 bottom
R3001  NC 5.1K_2  [0402]  18.8 78.77 180 bottom
R3002  49.9/F_2  [0402]  34.16 76.33 315 bottom
R3003  220nH/1.25A  [SL0603-H1_0]  15.64 67.67 90 bottom
R3004  NC 5.1K_2  [0402]  22.88 65.7 180 bottom
R3005  NC 0_1  [0201]  30.49 70.21 225 bottom
R3006  49.9/F_2  [0402]  31.79 74.1 315 bottom
R3007  10K_2  [0402]  29.6 69.79 315 bottom
R3008  10K_2  [0402]  41.35 76.69 45 bottom
R3009  220nH/1.25A  [SL0603-H1_0]  16.25 60.74 270 bottom
R3010  NC 5.1K_2  [0402]  21.25 65.5 180 bottom
R3011  49.9/F_2  [0402]  32.25 64.7 45 bottom
R3012  NC 10K_2  [0402]  32.16 66.98 225 bottom
R3013  10K_2  [0402]  36.99 62.23 225 bottom
R3014  2.2K_2  [0402]  43.11 61.03 315 bottom
R3015  NC 1M_2  [0402]  30.42 71.14 225 bottom
R3016  NC 10K_2  [0402]  35.92 61.11 45 bottom
R3017  10K_2  [0402]  31.07 65.91 45 bottom
R3018  402/F_2  [0402]  31.62 71.74 135 bottom
R3019  0_2  [0402]  42.03 62.11 315 bottom
R3020  NC 5.1K_2  [0402]  22.64 53.41 180 bottom
R3021  0_2  [0402]  41.45 61.53 315 bottom
R3022  220nH/1.25A  [SL0603-H1_0]  16.26 57.7 90 bottom
R3023  49.9/F_2  [0402]  34.62 62.4 45 bottom
R3024  5.1K_2  [0402]  38.84 60.23 225 bottom
R3025  5.1K_2  [0402]  37.61 61.62 225 bottom
R3026  0_2  [0402]  37.77 59.11 225 bottom
R3027  0_2  [0402]  36.48 60.5 225 bottom
R3028  0_2  [0402]  38.18 60.85 225 bottom
R3029  10K_2  [0402]  28.95 75.54 0 top
R3030  100K_2  [0402]  28.95 76.39 180 top
R3031  2.2K_2  [0402]  42.51 60.46 315 bottom
R3032  5.1K_2  [0402]  26.85 78.06 180 top
R3033  0_2  [0402]  39.47 59.61 225 bottom
R3100  10K_2  [0402]  28.47 96.1 270 top
R3101  100K_2  [0402]  29.32 96.1 90 top
R3102  5.1K_2  [0402]  30.99 98.2 90 top
R3103  10K_2  [0402]  28.92 92.42 0 top
R3104  100K_2  [0402]  28.92 93.27 180 top
R3105  5.1K_2  [0402]  26.82 94.94 180 top
R3106  10K_2  [0402]  28.93 86.74 0 top
R3107  100K_2  [0402]  28.93 87.59 180 top
R3108  5.1K_2  [0402]  26.83 89.26 180 top
R3109  10K_2  [0402]  28.96 81.13 0 top
R3110  100K_2  [0402]  28.96 81.98 180 top
R3111  5.1K_2  [0402]  26.86 83.65 180 top
R3112  0_2  [0402]  38.53 53.29 180 bottom
R3113  0_2  [0402]  38.53 54.14 180 bottom
R3114  0_2  [0402]  38.53 51.59 180 bottom
R3115  0_2  [0402]  38.53 54.99 180 bottom
R3116  0_2  [0402]  38.53 56.69 180 bottom
R3118  1K_2  [0402]  42.14 62.5 0 top
R3200  1K_2  [0402]  56.68 60.49 90 bottom
R3201  33K/F_2  [0402]  53.13 60.48 90 bottom
R3202  100K_2  [0402]  54.98 60.49 270 bottom
R3203  47K/F_2  [0402]  53.98 60.49 270 bottom
R3204  1K_2  [0402]  49.02 103.62 180 bottom
R3205  100K_2  [0402]  47.47 103.62 0 bottom
R3208  1K_2  [0402]  57.05 105.42 180 bottom
R3221  10K_2  [0402]  28.91 69.31 0 top
R3222  100K_2  [0402]  28.91 70.16 180 top
R3223  5.1K_2  [0402]  26.81 71.83 180 top
R3224  10K_2  [0402]  28.95 63.44 0 top
R3225  100K_2  [0402]  28.95 64.29 180 top
R3226  5.1K_2  [0402]  26.85 65.96 180 top
R3227  10K_2  [0402]  28.95 56.72 0 top
R3228  100K_2  [0402]  28.95 57.57 180 top
R3229  5.1K_2  [0402]  26.85 59.24 180 top
R3300  120/F_5  [SR0805]  130.97 123.14 0 top
R3301  120/F_5  [SR0805]  146.72 122.07 0 top
R3302  120/F_5  [SR0805]  120.07 123.03 0 top
R3303  120/F_5  [SR0805]  111.11 123.03 180 top
R3401  3.3/F_2  [0402]  133.88 125.63 180 bottom
R3402  3.3/F_2  [0402]  132.37 125.62 0 bottom
R3403  NC 1M_2  [0402]  128.37 120.26 270 bottom
R3404  3.3/F_2  [0402]  125.65 125.6 180 bottom
R3405  3.3/F_2  [0402]  124.11 125.6 0 bottom
R3406  3.3/F_2  [0402]  118.07 125.6 180 bottom
R3407  3.3/F_2  [0402]  116.54 125.6 0 bottom
R3408  3.3/F_2  [0402]  110.89 125.61 180 bottom
R3409  3.3/F_2  [0402]  109.36 125.6 0 bottom
R3410  10K_2  [0402]  131.41 96.75 90 bottom
R3411  10K_2  [0402]  131.41 98.29 90 bottom
R3412  22_2  [0402]  137.5 105.9 0 bottom
R3413  10K_2  [0402]  108.95 91.75 180 bottom
R3414  10K_2  [0402]  111.05 92.3 180 bottom
R3415  10K_2  [0402]  125.51 95.91 90 bottom
R3416  10K_2  [0402]  125.49 98.27 90 bottom
R3417  22_2  [0402]  134.15 95.54 180 bottom
R3418  22_2  [0402]  132.61 95.55 0 bottom
R3419  22_2  [0402]  108.95 90.05 0 bottom
R3420  22_2  [0402]  108.95 90.9 0 bottom
R3421  22_2  [0402]  128.27 95.56 180 bottom
R3422  22_2  [0402]  126.74 95.55 0 bottom
R3425  22_2  [0402]  133.9 99.45 0 bottom
R3426  22_2  [0402]  113.4 90.7 90 bottom
R3496  NC 0_2  [0402]  112.75 106.35 0 bottom
R3497  NC 0_2  [0402]  112.3 107.6 270 bottom
R3498  NC 0_2  [0402]  129.35 106.3 90 bottom
R3499  NC 0_2  [0402]  128.15 105.8 0 bottom
R3500  470_2  [0402]  85.55 110.15 180 top
R3501  22_2  [0402]  87.25 96.65 0 top
R3502  2K/F_2  [0402]  85.15 113.75 270 top
R3503  3K/F_2  [0402]  85.15 111.35 270 top
R3504  0_2  [0402]  85.15 108.95 90 top
R3505  3K/F_2  [0402]  83.35 111.3 270 top
R3506  22_2  [0402]  91.9 91.3 90 top
R3507  22_2  [0402]  42.54 43.02 180 top
R3508  470_2  [0402]  82.95 110.1 180 top
R3509  22_2  [0402]  90.75 91.3 90 top
R3510  2K/F_2  [0402]  83.35 113.7 270 top
R3511  0_2  [0402]  83.35 108.9 90 top
R3512  22_2  [0402]  89.9 91.3 90 top
R3513  0_2  [0402]  87.25 93.05 0 top
R3514  0_2  [0402]  87.25 93.9 0 top
R3515  NC 0_2  [0402]  85.7 94.75 0 top
R3516  NC 0_2  [0402]  85.7 95.7 0 top
R3517  470_2  [0402]  77.15 110.1 180 top
R3518  4.7K_2  [0402]  87.25 94.75 0 top
R3519  4.7K_2  [0402]  87.25 95.7 0 top
R3520  2K/F_2  [0402]  76.75 113.7 270 top
R3521  3K/F_2  [0402]  76.75 111.3 270 top
R3522  0_2  [0402]  76.75 108.9 90 top
R3523  2K/F_2  [0402]  75.05 113.7 270 top
R3524  3K/F_2  [0402]  75.05 111.3 270 top
R3525  0_2  [0402]  75.05 108.9 90 top
R3526  470_2  [0402]  74.65 110.1 180 top
R3527  NC 10K_2  [0402]  50.33 108.09 270 top
R3528  22_2  [0402]  47.92 113.42 180 top
R3529  22_2  [0402]  55.57 111.87 180 top
R3530  22_2  [0402]  55.57 110.77 180 top
R3531  22_2  [0402]  47.92 112.37 180 top
R3532  NC 4.7K_2  [0402]  52.1 108.09 90 top
R3533  22_2  [0402]  47.92 111.37 180 top
R3534  4.7K_2  [0402]  51.2 108.09 90 top
R3535  4.7K_2  [0402]  52.1 106.54 90 top
R3536  NC 4.7K_2  [0402]  51.2 106.54 90 top
R3537  22_2  [0402]  47.95 110.3 180 top
R3606  200K_2  [0402]  131.49 7.24 90 top
R3608  10K_2  [0402]  169.7 7.98 270 top
R3622  10K_2  [0402]  172.25 7.97 270 top
R3623  10K_2  [0402]  185.24 8.01 270 top
R3624  10K_2  [0402]  187.78 7.97 270 top
R3627  4.7K_2  [0402]  131.01 9.66 180 top
R3628  4.7K_2  [0402]  131.01 8.81 180 top
R3629  21.5K/F_2  [0402]  132.97 16.57 270 top
R3630  33K/F_2  [0402]  137.42 12.05 180 top
R3631  10K_2  [0402]  130.28 13.89 0 top
R3633  0_2  [0402]  133.87 9.44 90 top
R3634  0_2  [0402]  133.02 9.44 90 top
R3635  0_2  [0402]  134.77 16.57 90 top
R3636  0_2  [0402]  137.42 13.05 0 top
R3901  2.2K_2  [0402]  127.64 111.6 90 top
R3903  2.2K_2  [0402]  127.64 109.5 270 top
R3909  22_2  [0402]  129.77 109.92 180 top
R3910  22_2  [0402]  129.77 111.17 180 top
R3915  120/F_5  [SR0805]  100.4 123.07 180 top
R4000  10K_2  [0402]  134.23 117.51 0 top
R4001  10K_2  [0402]  134.23 118.81 0 top
R4002  10K_2  [0402]  136.82 103.94 270 top
R4003  5.1K_2  [0402]  139.21 111.75 90 top
R4004  10K_2  [0402]  137.65 104.57 270 top
R4005  10K_2  [0402]  131.15 104.17 270 top
R4006  0_2  [0402]  135.2 102.72 90 top
R4007  0_2  [0402]  129.45 102.67 90 top
R4008  10K_2  [0402]  136.82 105.99 90 top
R4009  10K_2  [0402]  131.12 105.79 90 top
R4010  10K_2  [0402]  130.3 102.67 270 top
RT2300  100K/F_2T  [0402]  125.46 34.59 0 top
RT2400  100K/F_2T  [0402]  42.22 34.79 180 top
SW500  TSK-051510-160-KJ  [SW4-H1_5-TSK-051510-160-KJ]  184.05 125.18 0 top
SW501  DHN_02_V-TR  [DSW4-1_27H1_5-DHN-02]  158.82 35.07 0 top
SW3300  DS-D1-06-G  [SW12-H2_3-DS-D1-06-G]  121.06 115.94 180 top
TP500  2.0mm  [TP2_0]  183.2 10.8 180 top
TP501  2.0mm  [TP2_0]  178.16 28.4 180 top
TP502  0.5mm  [TP0_5]  125.85 22.63 180 top
TP602  0.5mm  [TP0_5]  66.65 51.07 180 bottom
TP603  0.5mm  [TP0_5]  70.49 48.46 270 bottom
TP700  0.5mm  [TP0_5]  102.23 25.25 270 bottom
TP801  1.0mm  [TP1_0]  52.39 107.9 180 bottom
TP802  1.0mm  [TP1_0]  139.05 85.87 0 top
TP804  1.0mm  [TP1_0]  45.35 55.93 90 bottom
TP805  1.0mm  [TP1_0]  50.74 43.89 0 bottom
TP806  1.0mm  [TP1_0]  45.55 51.36 90 bottom
TP900  0.5mm  [TP0_5]  43.13 13.18 0 bottom
TP901  1.0mm  [TP1_0]  21.66 12.2 180 top
TP902  0.5mm  [TP0_5]  42.77 15.02 0 bottom
TP903  0.5mm  [TP0_5]  44.79 15.02 0 bottom
TP904  1.0mm  [TP1_0]  44.88 18.04 180 bottom
TP905  1.0mm  [TP1_0]  44.81 19.94 180 bottom
TP906  1.0mm  [TP1_0]  44.77 21.82 180 bottom
TP907  1.0mm  [TP1_0]  44.81 23.83 180 bottom
TP908  1.0mm  [TP1_0]  31.77 25.8 180 bottom
TP909  1.0mm  [TP1_0]  19.72 11.52 180 top
TP910  0.5mm  [TP0_5]  46.35 22.77 180 bottom
TP911  1.0mm  [TP1_0]  23.06 14.12 180 top
TP1000  0.5mm  [TP0_5]  48.3 34.87 180 bottom
TP1001  0.5mm  [TP0_5]  49.51 34.87 180 bottom
TP1002  0.5mm  [TP0_5]  46.9 34.82 180 bottom
TP1003  1.0mm  [TP1_0]  47.1 30.4 0 bottom
TP1004  1.0mm  [TP1_0]  45.57 29.38 0 bottom
TP1005  1.0mm  [TP1_0]  46.4 27.69 0 bottom
TP1006  1.0mm  [TP1_0]  46.69 24.6 0 bottom
TP1007  1.0mm  [TP1_0]  60.19 24.7 0 bottom
TP1008  0.5mm  [TP0_5]  47.75 27.27 180 bottom
TP1100  0.5mm  [TP0_5]  33.21 47.51 180 bottom
TP1101  1.0mm  [TP1_0]  30.86 44.25 0 bottom
TP1102  0.5mm  [TP0_5]  34.17 45.35 180 bottom
TP1103  0.5mm  [TP0_5]  32.23 45.66 180 bottom
TP1104  1.0mm  [TP1_0]  32.24 41.86 0 bottom
TP1105  1.0mm  [TP1_0]  30.62 40.93 0 bottom
TP1106  1.0mm  [TP1_0]  30.49 39.05 0 bottom
TP1107  1.0mm  [TP1_0]  30.49 37.1 0 bottom
TP1108  1.0mm  [TP1_0]  28.94 47 90 bottom
TP1109  1.0mm  [TP1_0]  45.85 33.72 0 bottom
TP1110  0.5mm  [TP0_5]  32.45 38.37 180 bottom
TP1111  1.0mm  [TP1_0]  28.97 42.6 90 bottom
TP1200  1.0mm  [TP1_0]  18.14 12.83 270 top
TP1201  1.0mm  [TP1_0]  24.6 16.12 270 top
TP1202  1.0mm  [TP1_0]  25.82 37.21 0 top
TP1203  1.0mm  [TP1_0]  25.86 34.93 90 top
TP1204  1.0mm  [TP1_0]  30.03 37.11 0 top
TP1205  1.0mm  [TP1_0]  47.26 32.21 0 bottom
TP1206  1.0mm  [TP1_0]  63.25 31.81 0 bottom
TP1300  1.0mm  [TP1_0]  26.7 49.82 0 top
TP1301  1.0mm  [TP1_0]  25.63 47.51 0 top
TP1400  1.0mm  [TP1_0]  99.05 98.32 180 top
TP1401  1.0mm  [TP1_0]  90.48 104.66 180 top
TP1402  1.0mm  [TP1_0]  91.44 106.45 180 top
TP1403  0.5mm  [TP0_5]  89.64 109.05 180 top
TP1404  1.0mm  [TP1_0]  93.85 112.93 180 top
TP1600  1.0mm  [TP1_0]  130.1 66.98 270 top
TP1700  -  [TP0_5]  137 65.4 0 top
TP1701  -  [TP0_5]  138.07 65.4 0 top
TP1800  1.0mm  [TP1_0]  125.35 56.47 0 top
TP1801  1.0mm  [TP1_0]  98.6 19.8 180 bottom
TP1802  -  [TP0_5]  149.25 84.77 0 top
TP1803  -  [TP0_5]  149.25 83.97 0 top
TP1808  0.8mm  [TP0_8]  139.95 27.67 0 top
TP2400  -  [TP0_5]  147.15 94.07 0 top
TP2401  -  [TP0_5]  148.95 95.73 270 top
TP2402  -  [TP0_5]  150.42 83.88 0 top
TP2403  -  [TP0_5]  150.61 82.74 0 top
TP2404  -  [TP0_5]  150.9 81.55 0 top
TP2405  -  [TP0_5]  151.7 82.31 0 top
TP2406  -  [TP0_5]  151.98 81.18 0 top
TP2407  -  [TP0_5]  152.21 80.04 0 top
TP2408  -  [TP0_5]  153.31 81.05 0 top
TP2409  -  [TP0_5]  153.55 79.99 0 top
TP2410  -  [TP0_5]  155.03 81.01 0 top
TP2411  1.0mm  [TP1_0]  164.02 81.29 0 top
TP2412  1.0mm  [TP1_0]  164 83.47 0 top
TP2413  1.0mm  [TP1_0]  156.5 79.13 0 top
TP2414  1.0mm  [TP1_0]  156.78 80.72 0 top
TP2500  1.0mm  [TP1_0]  135.45 59.02 0 bottom
TP2501  1.0mm  [TP1_0]  135.4 57.17 0 bottom
TP2502  1.0mm  [TP1_0]  128.95 52.37 0 bottom
TP2600  0.5mm  [TP0_5]  42.57 39.41 180 top
TP2601  0.5mm  [TP0_5]  43.61 37.51 180 top
TP2603  0.5mm  [TP0_5]  98.7 93.85 0 bottom
TP2604  0.5mm  [TP0_5]  100.1 95.05 0 bottom
TP2605  0.5mm  [TP0_5]  98.7 95.05 0 bottom
TP2608  0.5mm  [TP0_5]  42.43 40.92 180 top
TP2609  0.5mm  [TP0_5]  41.68 40.05 180 top
TP2610  0.5mm  [TP0_5]  41.7 38.95 180 top
TP2612  0.5mm  [TP0_5]  42.95 51.3 180 top
TP2613  0.5mm  [TP0_5]  133.78 90.56 180 bottom
TP2614  0.5mm  [TP0_5]  132.63 90.52 180 bottom
TP2615  0.5mm  [TP0_5]  42.96 48.41 0 top
TP2616  0.5mm  [TP0_5]  42.94 46.91 0 top
TP2617  0.5mm  [TP0_5]  42.92 45.44 0 top
TP2618  0.5mm  [TP0_5]  41.64 44.01 0 top
TP2619  0.5mm  [TP0_5]  134.29 89.66 180 bottom
TP2620  0.5mm  [TP0_5]  133.17 89.63 180 bottom
TP2622  0.5mm  [TP0_5]  42.91 53.79 0 top
TP2623  0.5mm  [TP0_5]  42.95 52.41 0 top
TP2625  0.5mm  [TP0_5]  43.82 53.14 0 top
TP2626  0.5mm  [TP0_5]  43.92 49.08 0 top
TP2627  0.5mm  [TP0_5]  43.92 47.64 0 top
TP2628  0.5mm  [TP0_5]  43.86 44.9 0 top
TP2629  0.5mm  [TP0_5]  41.68 41.95 0 top
TP2630  0.5mm  [TP0_5]  42.62 19.26 0 top
TP2631  0.5mm  [TP0_5]  44.49 36.37 0 top
TP2632  0.5mm  [TP0_5]  43.7 35.5 0 top
TP2700  0.5mm  [TP0_5]  118.67 43.17 180 bottom
TP2701  0.5mm  [TP0_5]  117.4 43.17 180 bottom
TP2702  0.5mm  [TP0_5]  60.85 117.52 0 top
TP2800  0.5mm  [TP0_5]  84.6 95.5 90 bottom
TP2804  0.8mm  [TP0_8]  109.5 18.3 0 bottom
TP3200  1.0mm  [TP1_0]  48.5 66.02 90 bottom
TP3201  1.0mm  [TP1_0]  40.8 106.37 180 bottom
TP3400  0.5mm  [TP0_5]  108.75 107.25 180 bottom
TP3401  0.5mm  [TP0_5]  133.1 94.45 180 bottom
TP3402  0.5mm  [TP0_5]  126.55 105.7 180 bottom
TP3403  0.5mm  [TP0_5]  135.05 94.45 180 bottom
TP3404  0.5mm  [TP0_5]  106.65 101 180 bottom
TP3405  0.5mm  [TP0_5]  106.15 93.1 180 bottom
TP3406  0.5mm  [TP0_5]  130.05 96.65 180 bottom
TP3407  0.5mm  [TP0_5]  134.05 101.2 180 bottom
TP3499  0.8mm  [TP0_8]  142.85 29.77 0 top
TP3500  0.8mm  [TP0_8]  85.15 105.55 270 top
TP3501  0.8mm  [TP0_8]  83.35 105.55 270 top
TP3502  0.8mm  [TP0_8]  76.75 105.55 270 top
TP3503  0.8mm  [TP0_8]  75.05 105.55 270 top
TP3504  0.5mm  [TP0_5]  96.35 95.6 180 top
TP3505  0.8mm  [TP0_8]  80.15 105.55 270 top
TP3506  0.5mm  [TP0_5]  92.75 89.6 180 top
TP3507  0.8mm  [TP0_8]  58.82 113.45 180 top
TP3508  0.8mm  [TP0_8]  57.61 112.6 180 top
TP3509  0.8mm  [TP0_8]  58.48 111.41 180 top
TP3510  0.8mm  [TP0_8]  95.05 90.7 180 top
TP3511  0.5mm  [TP0_5]  57.09 111.01 270 top
TP3512  0.5mm  [TP0_5]  52.7 118.83 0 top
TP3513  0.5mm  [TP0_5]  57.36 114.32 270 top
TVS1202  ESD54231N-2/TR  [ESD0402H0_55-ESD54231]  20.95 15.69 90 top
TVS1203  ESD54231N-2/TR  [ESD0402H0_55-ESD54231]  21.9 15.69 90 top
TVS1204  ESD54231N-2/TR  [ESD0402H0_55-ESD54231]  18.15 15.69 90 top
TVS1205  ESD54231N-2/TR  [ESD0402H0_55-ESD54231]  19.12 15.69 90 top
TVS1206  ESD54231N-2/TR  [ESD0402H0_55-ESD54231]  20.01 15.68 90 top
TVS1209  ESD54231N-2/TR  [ESD0402H0_55-ESD54231]  24 38.62 180 top
TVS1210  ESD54231N-2/TR  [ESD0402H0_55-ESD54231]  24 36.67 180 top
TVS1211  ESD54231N-2/TR  [ESD0402H0_55-ESD54231]  24 34.88 180 top
TVS1212  ESD54231N-2/TR  [ESD0402H0_55-ESD54231]  24 35.79 180 top
TVS1213  ESD54231N-2/TR  [ESD0402H0_55-ESD54231]  24 39.72 180 top
TVS1302  ESD54231N-2/TR  [ESD0402H0_55-ESD54231]  23.71 50.28 180 top
TVS1303  ESD54231N-2/TR  [ESD0402H0_55-ESD54231]  23.71 49.36 180 top
TVS1304  ESD54231N-2/TR  [ESD0402H0_55-ESD54231]  23.73 47.49 180 top
TVS1305  ESD54231N-2/TR  [ESD0402H0_55-ESD54231]  23.72 48.39 180 top
TVS1306  ESD54231N-2/TR  [ESD0402H0_55-ESD54231]  23.71 51.23 180 top
TVS1500  ESD54231N-2/TR  [ESD0402H0_55-ESD54231]  16.55 96.35 180 top
TVS1501  ESD54231N-2/TR  [ESD0402H0_55-ESD54231]  21.6 114.15 180 top
TVS1502  ESD54231N-2/TR  [ESD0402H0_55-ESD54231]  16.59 98.64 180 top
TVS1800  ESD54231N-2/TR  [ESD0402H0_55-ESD54231]  148.85 39.45 270 top
TVS1801  ESD54231N-2/TR  [ESD0402H0_55-ESD54231]  148.87 29.51 90 top
TVS1802  ESD54231N-2/TR  [ESD0402H0_55-ESD54231]  146.85 39.45 270 top
TVS1803  ESD54231N-2/TR  [ESD0402H0_55-ESD54231]  146.87 29.49 90 top
TVS1804  ESD54231N-2/TR  [ESD0402H0_55-ESD54231]  140.85 39.47 270 top
TVS1805  ESD54231N-2/TR  [ESD0402H0_55-ESD54231]  140.85 29.47 90 top
TVS1806  ESD54231N-2/TR  [ESD0402H0_55-ESD54231]  138.85 39.47 270 top
TVS1807  ESD54231N-2/TR  [ESD0402H0_55-ESD54231]  137.07 29.85 0 top
TVS1808  ESD54231N-2/TR  [ESD0402H0_55-ESD54231]  135.46 29.85 180 top
TVS1809  ESD54231N-2/TR  [ESD0402H0_55-ESD54231]  136.85 39.47 270 top
TVS1810  ESD54231N-2/TR  [ESD0402H0_55-ESD54231]  134.85 39.47 270 top
TVS1900  ESD54231N-2/TR  [ESD0402H0_55-ESD54231]  165.99 113.65 0 top
TVS1901  ESD54231N-2/TR  [ESD0402H0_55-ESD54231]  169.04 90.03 90 top
TVS1902  ESD54231N-2/TR  [ESD0402H0_55-ESD54231]  172.06 78.11 90 top
TVS1903  ESD54231N-2/TR  [ESD0402H0_55-ESD54231]  172.34 100.86 90 top
TVS1904  ESD54231N-2/TR  [ESD0402H0_55-ESD54231]  172.07 79.64 270 top
TVS1906  ESD5311N  [DFN1006-2L-H0_5]  172.05 110.28 180 top
TVS1907  ESD5311N  [DFN1006-2L-H0_5]  171.81 91.04 180 top
TVS1908  ESD5311N  [DFN1006-2L-H0_5]  172.05 109.22 180 top
TVS1909  ESD5311N  [DFN1006-2L-H0_5]  171.77 89.99 180 top
TVS1910  ESD5311N  [DFN1006-2L-H0_5]  168.76 117.12 180 top
TVS1911  ESD5311N  [DFN1006-2L-H0_5]  168.63 94.58 180 top
TVS1912  ESD5311N  [DFN1006-2L-H0_5]  168.76 116 180 top
TVS1913  ESD5311N  [DFN1006-2L-H0_5]  168.63 93.46 180 top
TVS1914  ESD54231N-2/TR  [ESD0402H0_55-ESD54231]  175.55 83.02 270 bottom
TVS1915  ESD54231N-2/TR  [ESD0402H0_55-ESD54231]  175.55 105.02 270 bottom
TVS1916  ESD54231N-2/TR  [ESD0402H0_55-ESD54231]  175.55 106.92 270 bottom
TVS1917  ESD54231N-2/TR  [ESD0402H0_55-ESD54231]  175.55 85.07 270 bottom
TVS2000  ESD54231N-2/TR  [ESD0402H0_55-ESD54231]  169.97 43.84 90 top
TVS2001  ESD54231N-2/TR  [ESD0402H0_55-ESD54231]  171.96 56.71 90 top
TVS2002  ESD54231N-2/TR  [ESD0402H0_55-ESD54231]  169.99 68.62 0 top
TVS2003  ESD54231N-2/TR  [ESD0402H0_55-ESD54231]  171.89 35.03 90 top
TVS2004  ESD54231N-2/TR  [ESD0402H0_55-ESD54231]  171.95 58.24 270 top
TVS2005  ESD54231N-2/TR  [ESD0402H0_55-ESD54231]  171.88 36.65 270 top
TVS2006  ESD5311N  [DFN1006-2L-H0_5]  171.97 70 270 top
TVS2007  ESD5311N  [DFN1006-2L-H0_5]  171.97 71.4 90 top
TVS2008  ESD5311N  [DFN1006-2L-H0_5]  171.9 45.74 270 top
TVS2009  ESD5311N  [DFN1006-2L-H0_5]  171.9 47.1 90 top
TVS2010  ESD5311N  [DFN1006-2L-H0_5]  171.97 66.84 270 top
TVS2011  ESD5311N  [DFN1006-2L-H0_5]  171.97 68.24 90 top
TVS2012  ESD5311N  [DFN1006-2L-H0_5]  171.85 48.52 270 top
TVS2013  ESD5311N  [DFN1006-2L-H0_5]  171.85 49.92 90 top
TVS2301  ESD5311N  [DFN1006-2L-H0_5]  156.3 47.39 90 bottom
TVS2302  ESD5311N  [DFN1006-2L-H0_5]  157.2 47.39 90 bottom
TVS2303  ESD5311N  [DFN1006-2L-H0_5]  158.1 47.39 90 bottom
TVS2306  ESD54231N-2/TR  [ESD0402H0_55-ESD54231]  145.24 47.73 270 bottom
TVS2309  ESD54231N-2/TR  [ESD0402H0_55-ESD54231]  147.49 47.72 270 bottom
TVS2500  ESD54231N-2/TR  [ESD0402H0_55-ESD54231]  175.5 63.62 270 bottom
TVS2501  ESD54231N-2/TR  [ESD0402H0_55-ESD54231]  175.5 61.47 270 bottom
TVS2502  ESD54231N-2/TR  [ESD0402H0_55-ESD54231]  175.6 42.22 270 bottom
TVS2503  ESD54231N-2/TR  [ESD0402H0_55-ESD54231]  175.6 39.97 270 bottom
TVS2504  ESD54231N-2/TR  [ESD0402H0_55-ESD54231]  138.85 29.47 90 top
TVS2505  ESD54231N-2/TR  [ESD0402H0_55-ESD54231]  144.85 39.45 270 top
TVS2506  ESD54231N-2/TR  [ESD0402H0_55-ESD54231]  144.85 29.5 90 top
TVS2507  ESD54231N-2/TR  [ESD0402H0_55-ESD54231]  142.85 39.45 270 top
TVS3400  ESD54231N-2/TR  [ESD0402H0_55-ESD54231]  133.16 121.63 0 bottom
TVS3401  ESD54231N-2/TR  [ESD0402H0_55-ESD54231]  124.96 121.64 0 bottom
TVS3402  ESD54231N-2/TR  [ESD0402H0_55-ESD54231]  117.38 121.64 0 bottom
TVS3403  ESD54231N-2/TR  [ESD0402H0_55-ESD54231]  110.14 121.62 0 bottom
TVS3500  ESD54231N-2/TR  [ESD0402H0_55-ESD54231]  46.82 123.21 90 top
TVS3501  ESD54231N-2/TR  [ESD0402H0_55-ESD54231]  28.37 123.22 90 top
TVS3502  ESD54231N-2/TR  [ESD0402H0_55-ESD54231]  45.56 123.22 90 top
TVS3503  ESD54231N-2/TR  [ESD0402H0_55-ESD54231]  27.12 123.22 90 top
TVS3504  ESD54231N-2/TR  [ESD0402H0_55-ESD54231]  44.3 123.22 90 top
TVS3505  ESD54231N-2/TR  [ESD0402H0_55-ESD54231]  25.87 123.22 90 top
TVS3506  ESD54231N-2/TR  [ESD0402H0_55-ESD54231]  43.05 123.22 90 top
TVS3507  ESD54231N-2/TR  [ESD0402H0_55-ESD54231]  24.63 123.2 90 top
TVS3614  ESD54231N-2/TR  [ESD0402H0_55-ESD54231]  170.6 7.95 270 top
TVS3615  ESD54231N-2/TR  [ESD0402H0_55-ESD54231]  173.1 7.97 270 top
